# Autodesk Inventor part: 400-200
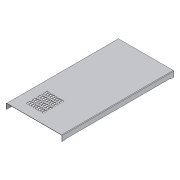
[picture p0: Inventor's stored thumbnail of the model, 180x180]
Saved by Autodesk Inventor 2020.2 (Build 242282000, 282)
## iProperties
Created: 2010-10
Part Number: 400-200
Material: St1203
Document SubType Name: Konstrukcje blachowe
Designer: F.Stasiak
Density: 7.85 g/cm^3
Sheet Metal Rule: Blacha stalowa 2.5 mm/Okrągły
Description: =Ściana lewa <WYSOKOŚĆ> x <SZEROKOŚĆ> perforowana
Appearance: Metal-Stal
Mass: 5132.38 g
Surface Area: 5358.89 cm^2
Volume: 653.807 cm^3
Company: Fabian Stasiak CAD Consulting
Manager: www.cadconsulting.pl
SZEROKOŚĆ: 500
WYSOKOŚĆ: 450
Author: F.Stasiak
Subject: Zbiór ćwiczeń. Autodesk Inventor 2020. Kurs podstawowy
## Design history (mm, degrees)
node "Powierzchnia1"
  sketch "Szkic1"
    geometry: L1 (-250, 450)-(250, 450); L2 (250, 450)-(250, 0); L3 (250, 0)-(-250, 0); L4 (-250, 0)-(-250, 450); 2 further points
    constraints: 8 end point, 2 parallel, 1 coincident, 1 horizontal, 1 midpoint, 1 perpendicular
    dimensions: "d0" = 500 distance of L2.end L3.end; "d1" = 450 distance of L1.end L2.end
node "Kołnierz1"
node "Kołnierz2"
feature "Zawinięcie obrzeża1" dims "d25" = 2.5 (= SzerokośćGięciaPodcięcia), "d26" = 1.25 (= GłębokośćGięciaPodcięcia), "d27" = 5 (= MinimalnaPozostałość), "d28" = 2.5 (= PromieńGięcia), "d29" = 10 (= 4 x Grubość), "d30" = 1.25 (= 0.5 x Grubość), "d31" = 0.625 (= 0.5 x d30), "d54" = 2.5 (= Grubość), "OdstępPołączenia" = 0.01
sketch "Szkic5"
  geometry: L1 (245, 0)-(-245, 0) reference; L2 (-245, 450)-(-245, 0) reference; L3 (-250, 0)-(-250, 450) reference; 2 further points
  dimensions: "d32" = 104 distance from line of point (-150, 104) L1; "d34" = 100 distance from line of L3 point (-150, 104)
feature "iFeature18:1" sketch "Szkic5"
sketch "Szkic6"
  geometry: L1 (-45, 450)-(-45, 0) reference; L2 (0, 0)-(-45, 0) reference; L3 (0, 0)-(0, 450) reference; L4 (0, 450)-(-45, 450) reference; L5 (-22.5, 450)-(-22.5, 0); 3 further points
  constraints: 2 end point, 2 midpoint, 2 point on line
  dimensions: "d45" = 130 distance from line of L4 point (-22.5, 320); "d46" = 150 distance of point (-22.5, 150) L5.end
hole "Hole1" sketch "Szkic6" at (-22.5, 320), (-22.5, 150) diameter "d47" = 12; stored, may be unused: countersink angle "d51" = 90 deg, drill point angle "d53" = 118 deg; dims "d48" = 6, "d49" = 4, "d50" = 2, "d52" = 2.5 (= Grubość)
node "Bryła1"
pattern_linear "Szyk prostokątny1" dims "d41" = 20, "d44" = 50
feature "Płyta1" dims "d54" = 2.5 (= Grubość)
sketch "Szkic2"
  geometry: L1 (0, -50)-(450, -50); L2 (450, -50)-(450, 0); 1 other entity
  constraints: 4 end point, 4 other
feature "Płyta2" dims "d3" = 2.5 (= SzerokośćGięciaPodcięcia), "d4" = 1.25 (= GłębokośćGięciaPodcięcia), "d5" = 5 (= MinimalnaPozostałość), "d6" = 2.5 (= PromieńGięcia), "d7" = 50, "d8" = 90 deg, "d9" = 2.5 (= PromieńGięcia), "d10" = 10 (= RozmiarPodcięciaNarożnika), "d11" = 2.5 (= Wielk_odstępu), "d12" = 2.5 (= Rozmiar_promienia_Jacobiego), "d54" = 2.5 (= Grubość), "OdstępPołączenia" = 0.01
feature "Gięcie1" dims "d3" = 2.5 (= SzerokośćGięciaPodcięcia), "d4" = 1.25 (= GłębokośćGięciaPodcięcia), "d5" = 5 (= MinimalnaPozostałość), "d6" = 2.5 (= PromieńGięcia), "d7" = 50, "d8" = 90 deg, "d9" = 2.5 (= PromieńGięcia), "d54" = 2.5 (= Grubość), "OdstępPołączenia" = 0.01
feature "Narożnik1" dims "d7" = 50, "d8" = 90 deg, "d10" = 10 (= RozmiarPodcięciaNarożnika), "d11" = 2.5 (= Wielk_odstępu), "d12" = 2.5 (= Rozmiar_promienia_Jacobiego)
sketch "Szkic3"
  geometry: L1 (0, 418)-(0, 32); L2 (0, 32)-(20, 32); L3 (20, 32)-(20, 418); L4 (20, 418)-(0, 418)
  constraints: 8 end point
feature "Płyta3" dims "d13" = 2.5 (= SzerokośćGięciaPodcięcia), "d14" = 1.25 (= GłębokośćGięciaPodcięcia), "d15" = 5 (= MinimalnaPozostałość), "d16" = 2.5 (= PromieńGięcia), "d17" = 32, "d18" = 32, "d19" = 20, "d20" = 90 deg, "d21" = 2.5 (= PromieńGięcia), "d22" = 10 (= RozmiarPodcięciaNarożnika), "d23" = 2.5 (= Wielk_odstępu), "d24" = 2.5 (= Rozmiar_promienia_Jacobiego), "d54" = 2.5 (= Grubość), "OdstępPołączenia" = 0.01
feature "Gięcie2" dims "d13" = 2.5 (= SzerokośćGięciaPodcięcia), "d14" = 1.25 (= GłębokośćGięciaPodcięcia), "d15" = 5 (= MinimalnaPozostałość), "d16" = 2.5 (= PromieńGięcia), "d19" = 20, "d20" = 90 deg, "d21" = 2.5 (= PromieńGięcia), "d54" = 2.5 (= Grubość), "OdstępPołączenia" = 0.01
feature "Narożnik2" dims "d19" = 20, "d20" = 90 deg, "d22" = 10 (= RozmiarPodcięciaNarożnika), "d23" = 2.5 (= Wielk_odstępu), "d24" = 2.5 (= Rozmiar_promienia_Jacobiego)
node "Pętla rzutowana1"
sketch "Szkic4"
  geometry: L1 (0, -2.5)-(0, 0); L2 (0, 1.25)-(-6.875, 1.25); L3 (-6.875, 1.25)-(-6.875, 3.75); L4 (-6.875, 3.75)-(0, 3.75); A1 r 0.625 centre (0, 0.625) between (0, 0) and (0, 1.25); A2 r 3.125 centre (0, 0.625) between (0, -2.5) and (0, 3.75)
  constraints: 8 end point, 4 point on circle
other parameters: "Grubość" = 2.5 (derived), "WspółczynnikK" = 4.4, "PromieńGięcia" = 2.5 (= Grubość), "SzerokośćGięciaPodcięcia" = 2.5 (= Grubość), "GłębokośćGięciaPodcięcia" = 1.25 (= 0.5 x Grubość), "MinimalnaPozostałość" = 5 (= 2 x Grubość), "PromieńPrzejścia" = 2.5 (= PromieńGięcia), "Rozmiar_promienia_Jacobiego" = 2.5 (= PromieńGięcia), "Wielk_odstępu" = 2.5 (= Grubość), "d2" = 2.5 (= PromieńGięcia), "d38" = 90 deg
